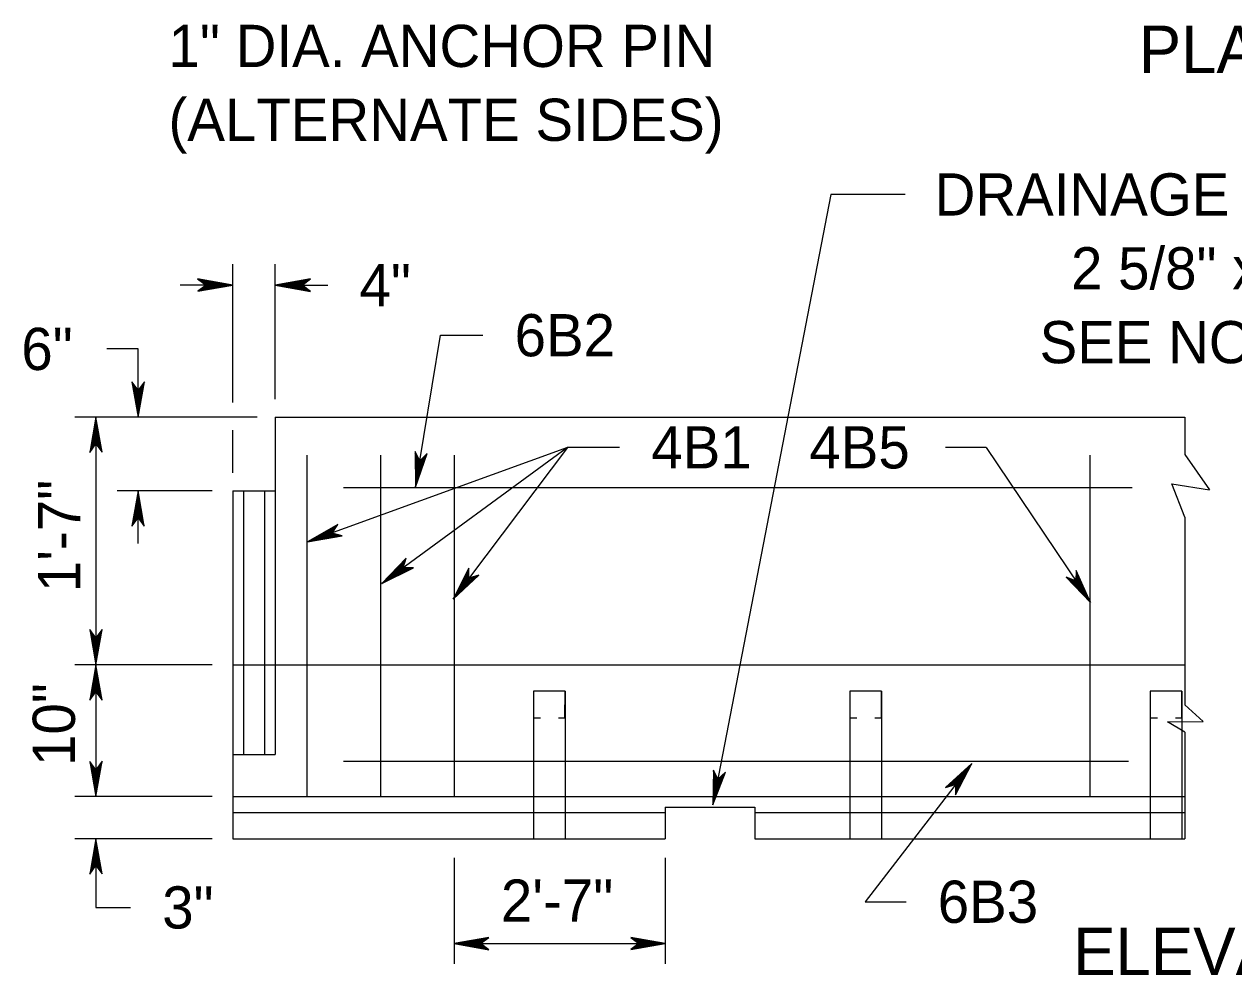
# Model space of a CAD drawing. Extents: x 499866 to 500993, y 499985 to 500645.
# Drawn here: x 500246.6 to 500361.2, y 500116.7 to 500206.9 of the extents above; entities that cross this region are included whole.
import ezdxf

# ---------------------------------------------------------------- set-up
doc = ezdxf.new("R2010")
doc.units = 0
doc.layers.add('24', color=7, linetype='Continuous')
doc.layers.add('5', color=7, linetype='Continuous')

msp = doc.modelspace()

# ---------------------------------------------------------------- linework, layer by layer
at = {"layer": '24'}
for points in [[(500266.37, 500182.17), (500263.02, 500182.77), (500263.82, 500182.17), (500263.03, 500181.59), (500266.37, 500182.17), (500266.15, 500182.17), (500263.11, 500182.72), (500263.88, 500182.17), (500263.17, 500181.64), (500266.02, 500182.16), (500265.91, 500182.17), (500263.31, 500182.64), (500263.9, 500182.17), (500263.3, 500181.71), (500265.86, 500182.18), (500265.75, 500182.16), (500263.48, 500182.57), (500263.92, 500182.18), (500263.47, 500181.77), (500265.43, 500182.16), (500265.24, 500182.16), (500263.65, 500182.48), (500263.96, 500182.18), (500263.62, 500181.85), (500265.2, 500182.17), (500265.03, 500182.19), (500263.83, 500182.39), (500264.06, 500182.16), (500263.81, 500181.93), (500264.86, 500182.17), (500264.69, 500182.19), (500263.97, 500182.33), (500264.09, 500182.17), (500263.9, 500181.99), (500264.61, 500182.18), (500264.14, 500182.29), (500264.2, 500182.16), (500264, 500182.03), (500264.49, 500182.16), (500264.18, 500182.23), (500264.31, 500182.13), (500264.16, 500182.07), (500264.31, 500182.17), (500264.23, 500182.18)], [(500270.36, 500182.17), (500273.71, 500181.58), (500272.91, 500182.17), (500273.7, 500182.76), (500270.36, 500182.17), (500270.59, 500182.18), (500273.62, 500181.63), (500272.85, 500182.18), (500273.56, 500182.71), (500270.71, 500182.19), (500270.82, 500182.17), (500273.42, 500181.71), (500272.83, 500182.18), (500273.43, 500182.64), (500270.87, 500182.17), (500270.98, 500182.19), (500273.25, 500181.78), (500272.81, 500182.17), (500273.26, 500182.58), (500271.3, 500182.19), (500271.49, 500182.19), (500273.08, 500181.87), (500272.77, 500182.17), (500273.11, 500182.5), (500271.53, 500182.17), (500271.71, 500182.16), (500272.9, 500181.96), (500272.67, 500182.19), (500272.92, 500182.42), (500271.87, 500182.17), (500272.04, 500182.16), (500272.76, 500182.02), (500272.64, 500182.18), (500272.83, 500182.36), (500272.13, 500182.17), (500272.59, 500182.06), (500272.53, 500182.19), (500272.73, 500182.32), (500272.24, 500182.19), (500272.55, 500182.11), (500272.42, 500182.22), (500272.57, 500182.28), (500272.42, 500182.18), (500272.5, 500182.17)], [(500283.66, 500163.04), (500286.03, 500177.43), (500290.06, 500177.43)], [(500257.37, 500169.67), (500257.97, 500173.02), (500257.37, 500172.21), (500256.79, 500173), (500257.37, 500169.67), (500257.37, 500169.89), (500257.92, 500172.92), (500257.37, 500172.15), (500256.84, 500172.86), (500257.36, 500170.01), (500257.37, 500170.12), (500257.84, 500172.72), (500257.37, 500172.13), (500256.91, 500172.73), (500257.37, 500170.17), (500257.36, 500170.28), (500257.77, 500172.55), (500257.37, 500172.11), (500256.97, 500172.56), (500257.36, 500170.6), (500257.36, 500170.79), (500257.68, 500172.38), (500257.38, 500172.08), (500257.05, 500172.41), (500257.37, 500170.83), (500257.38, 500171.01), (500257.59, 500172.2), (500257.36, 500171.97), (500257.13, 500172.22), (500257.37, 500171.17), (500257.39, 500171.34), (500257.53, 500172.06), (500257.37, 500171.94), (500257.19, 500172.14), (500257.37, 500171.43), (500257.49, 500171.9), (500257.36, 500171.83), (500257.23, 500172.03), (500257.36, 500171.54), (500257.43, 500171.85), (500257.33, 500171.72), (500257.27, 500171.87), (500257.37, 500171.72), (500257.38, 500171.8)], [(500253.38, 500169.67), (500252.79, 500166.31), (500253.38, 500167.12), (500253.96, 500166.33), (500253.38, 500169.67), (500253.38, 500169.44), (500252.83, 500166.41), (500253.38, 500167.18), (500253.91, 500166.47), (500253.39, 500169.32), (500253.38, 500169.21), (500252.92, 500166.61), (500253.38, 500167.2), (500253.84, 500166.6), (500253.38, 500169.16), (500253.39, 500169.05), (500252.98, 500166.78), (500253.38, 500167.22), (500253.79, 500166.77), (500253.39, 500168.73), (500253.39, 500168.54), (500253.07, 500166.95), (500253.37, 500167.25), (500253.7, 500166.92), (500253.38, 500168.5), (500253.37, 500168.32), (500253.16, 500167.13), (500253.39, 500167.36), (500253.62, 500167.11), (500253.38, 500168.16), (500253.36, 500167.99), (500253.22, 500167.27), (500253.38, 500167.39), (500253.56, 500167.19), (500253.38, 500167.9), (500253.27, 500167.43), (500253.39, 500167.5), (500253.52, 500167.3), (500253.39, 500167.79), (500253.32, 500167.48), (500253.42, 500167.61), (500253.48, 500167.46), (500253.38, 500167.61), (500253.37, 500167.53)], [(500283.66, 500163.04), (500284.78, 500166.22), (500284.07, 500165.53), (500283.63, 500166.39), (500283.66, 500163.04), (500283.69, 500163.26), (500284.72, 500166.14), (500284.06, 500165.47), (500283.65, 500166.25), (500283.7, 500163.38), (500283.74, 500163.48), (500284.61, 500165.95), (500284.05, 500165.46), (500283.71, 500166.12), (500283.75, 500163.53), (500283.75, 500163.64), (500284.51, 500165.8), (500284.06, 500165.43), (500283.73, 500165.94), (500283.8, 500163.96), (500283.83, 500164.15), (500284.4, 500165.65), (500284.06, 500165.4), (500283.79, 500165.78), (500283.85, 500164.18), (500283.89, 500164.35), (500284.28, 500165.49), (500284.02, 500165.3), (500283.83, 500165.58), (500283.91, 500164.51), (500283.95, 500164.67), (500284.2, 500165.36), (500284.02, 500165.27), (500283.88, 500165.49), (500283.95, 500164.76), (500284.13, 500165.2), (500284, 500165.16), (500283.9, 500165.38), (500283.95, 500164.88), (500284.07, 500165.17), (500283.95, 500165.06), (500283.92, 500165.21), (500283.99, 500165.05), (500284.02, 500165.13)], [(500257.37, 500162.67), (500256.78, 500159.32), (500257.37, 500160.12), (500257.96, 500159.34), (500257.37, 500162.67), (500257.38, 500162.45), (500256.83, 500159.41), (500257.38, 500160.18), (500257.91, 500159.47), (500257.39, 500162.33), (500257.37, 500162.22), (500256.91, 500159.62), (500257.38, 500160.2), (500257.84, 500159.6), (500257.37, 500162.17), (500257.39, 500162.05), (500256.98, 500159.78), (500257.37, 500160.22), (500257.78, 500159.77), (500257.39, 500161.73), (500257.39, 500161.54), (500257.06, 500159.95), (500257.36, 500160.26), (500257.7, 500159.93), (500257.37, 500161.51), (500257.36, 500161.33), (500257.16, 500160.13), (500257.39, 500160.36), (500257.62, 500160.11), (500257.37, 500161.16), (500257.36, 500161), (500257.22, 500160.28), (500257.38, 500160.4), (500257.56, 500160.2), (500257.37, 500160.91), (500257.26, 500160.44), (500257.39, 500160.51), (500257.52, 500160.3), (500257.39, 500160.79), (500257.31, 500160.48), (500257.42, 500160.61), (500257.48, 500160.46), (500257.38, 500160.61), (500257.36, 500160.53)], [(500273.44, 500157.83), (500276.72, 500158.41), (500275.78, 500158.68), (500276.31, 500159.48), (500273.44, 500157.83), (500273.64, 500157.91), (500276.62, 500158.42), (500275.72, 500158.67), (500276.2, 500159.39), (500273.75, 500157.96), (500273.86, 500157.98), (500276.4, 500158.43), (500275.71, 500158.66), (500276.11, 500159.28), (500273.91, 500158), (500274, 500158.05), (500276.23, 500158.44), (500275.69, 500158.65), (500275.97, 500159.17), (500274.3, 500158.16), (500274.47, 500158.22), (500276.04, 500158.46), (500275.66, 500158.63), (500275.85, 500159.05), (500274.51, 500158.22), (500274.68, 500158.27), (500275.84, 500158.48), (500275.56, 500158.62), (500275.71, 500158.91), (500274.82, 500158.33), (500274.99, 500158.38), (500275.69, 500158.49), (500275.53, 500158.6), (500275.65, 500158.83), (500275.06, 500158.42), (500275.53, 500158.47), (500275.42, 500158.57), (500275.57, 500158.76), (500275.16, 500158.48), (500275.47, 500158.51), (500275.32, 500158.56), (500275.43, 500158.66), (500275.33, 500158.53), (500275.41, 500158.54)], [(500273.44, 500157.83), (500276.72, 500158.41), (500275.78, 500158.68), (500276.31, 500159.48), (500273.44, 500157.83), (500273.64, 500157.91), (500276.62, 500158.42), (500275.72, 500158.67), (500276.2, 500159.39), (500273.75, 500157.96), (500273.86, 500157.98), (500276.4, 500158.43), (500275.71, 500158.66), (500276.11, 500159.28), (500273.91, 500158), (500274, 500158.05), (500276.23, 500158.44), (500275.69, 500158.65), (500275.97, 500159.17), (500274.3, 500158.16), (500274.47, 500158.22), (500276.04, 500158.46), (500275.66, 500158.63), (500275.85, 500159.05), (500274.51, 500158.22), (500274.68, 500158.27), (500275.84, 500158.48), (500275.56, 500158.62), (500275.71, 500158.91), (500274.82, 500158.33), (500274.99, 500158.38), (500275.69, 500158.49), (500275.53, 500158.6), (500275.65, 500158.83), (500275.06, 500158.42), (500275.53, 500158.47), (500275.42, 500158.57), (500275.57, 500158.76), (500275.16, 500158.48), (500275.47, 500158.51), (500275.32, 500158.56), (500275.43, 500158.66), (500275.33, 500158.53), (500275.41, 500158.54)], [(500280.49, 500153.9), (500283.48, 500155.37), (500282.5, 500155.37), (500282.78, 500156.28), (500280.49, 500153.9), (500280.67, 500154.03), (500283.38, 500155.35), (500282.45, 500155.34), (500282.7, 500156.17), (500280.75, 500154.11), (500280.85, 500154.16), (500283.17, 500155.3), (500282.44, 500155.33), (500282.64, 500156.04), (500280.89, 500154.19), (500280.97, 500154.27), (500283, 500155.26), (500282.42, 500155.31), (500282.54, 500155.89), (500281.22, 500154.45), (500281.37, 500154.56), (500282.81, 500155.23), (500282.4, 500155.28), (500282.47, 500155.74), (500281.41, 500154.57), (500281.56, 500154.66), (500282.62, 500155.19), (500282.3, 500155.24), (500282.37, 500155.57), (500281.68, 500154.77), (500281.82, 500154.85), (500282.47, 500155.16), (500282.28, 500155.22), (500282.33, 500155.47), (500281.88, 500154.91), (500282.32, 500155.1), (500282.19, 500155.16), (500282.28, 500155.38), (500281.97, 500155), (500282.25, 500155.11), (500282.09, 500155.12), (500282.17, 500155.25), (500282.11, 500155.09), (500282.18, 500155.12)], [(500280.49, 500153.9), (500283.48, 500155.37), (500282.5, 500155.37), (500282.78, 500156.28), (500280.49, 500153.9), (500280.67, 500154.03), (500283.38, 500155.35), (500282.45, 500155.34), (500282.7, 500156.17), (500280.75, 500154.11), (500280.85, 500154.16), (500283.17, 500155.3), (500282.44, 500155.33), (500282.64, 500156.04), (500280.89, 500154.19), (500280.97, 500154.27), (500283, 500155.26), (500282.42, 500155.31), (500282.54, 500155.89), (500281.22, 500154.45), (500281.37, 500154.56), (500282.81, 500155.23), (500282.4, 500155.28), (500282.47, 500155.74), (500281.41, 500154.57), (500281.56, 500154.66), (500282.62, 500155.19), (500282.3, 500155.24), (500282.37, 500155.57), (500281.68, 500154.77), (500281.82, 500154.85), (500282.47, 500155.16), (500282.28, 500155.22), (500282.33, 500155.47), (500281.88, 500154.91), (500282.32, 500155.1), (500282.19, 500155.16), (500282.28, 500155.38), (500281.97, 500155), (500282.25, 500155.11), (500282.09, 500155.12), (500282.17, 500155.25), (500282.11, 500155.09), (500282.18, 500155.12)], [(500287.23, 500152.42), (500289.66, 500154.69), (500288.73, 500154.41), (500288.73, 500155.36), (500287.23, 500152.42), (500287.35, 500152.6), (500289.57, 500154.64), (500288.68, 500154.37), (500288.69, 500155.23), (500287.41, 500152.7), (500287.49, 500152.77), (500289.38, 500154.53), (500288.67, 500154.35), (500288.67, 500155.09), (500287.52, 500152.81), (500287.57, 500152.91), (500289.23, 500154.44), (500288.66, 500154.33), (500288.61, 500154.92), (500287.77, 500153.16), (500287.88, 500153.31), (500289.07, 500154.36), (500288.65, 500154.3), (500288.59, 500154.75), (500287.91, 500153.33), (500288.02, 500153.46), (500288.89, 500154.27), (500288.57, 500154.23), (500288.54, 500154.56), (500288.11, 500153.6), (500288.22, 500153.72), (500288.75, 500154.2), (500288.56, 500154.2), (500288.53, 500154.46), (500288.26, 500153.79), (500288.62, 500154.1), (500288.48, 500154.12), (500288.51, 500154.35), (500288.32, 500153.9), (500288.56, 500154.09), (500288.4, 500154.05), (500288.44, 500154.2), (500288.43, 500154.03), (500288.49, 500154.08)], [(500347.63, 500152.09), (500346.28, 500155.14), (500346.24, 500154.16), (500345.34, 500154.48), (500347.63, 500152.09), (500347.5, 500152.27), (500346.3, 500155.04), (500346.27, 500154.11), (500345.45, 500154.4), (500347.43, 500152.36), (500347.38, 500152.46), (500346.34, 500154.82), (500346.28, 500154.09), (500345.58, 500154.33), (500347.35, 500152.5), (500347.28, 500152.59), (500346.37, 500154.65), (500346.3, 500154.08), (500345.72, 500154.22), (500347.1, 500152.85), (500347, 500153), (500346.4, 500154.47), (500346.32, 500154.06), (500345.87, 500154.14), (500346.99, 500153.04), (500346.91, 500153.19), (500346.42, 500154.27), (500346.36, 500153.96), (500346.04, 500154.03), (500346.81, 500153.32), (500346.73, 500153.46), (500346.45, 500154.12), (500346.38, 500153.94), (500346.13, 500154), (500346.67, 500153.52), (500346.5, 500153.96), (500346.44, 500153.84), (500346.22, 500153.94), (500346.59, 500153.61), (500346.49, 500153.9), (500346.47, 500153.74), (500346.34, 500153.83), (500346.5, 500153.76), (500346.47, 500153.83)], [(500253.38, 500146.18), (500253.97, 500149.53), (500253.38, 500148.73), (500252.79, 500149.52), (500253.38, 500146.18), (500253.37, 500146.41), (500253.93, 500149.44), (500253.37, 500148.67), (500252.84, 500149.38), (500253.36, 500146.53), (500253.38, 500146.64), (500253.84, 500149.24), (500253.37, 500148.65), (500252.92, 500149.25), (500253.38, 500146.69), (500253.36, 500146.8), (500253.77, 500149.07), (500253.38, 500148.63), (500252.97, 500149.08), (500253.36, 500147.12), (500253.36, 500147.31), (500253.69, 500148.9), (500253.39, 500148.59), (500253.05, 500148.93), (500253.38, 500147.35), (500253.39, 500147.52), (500253.59, 500148.72), (500253.36, 500148.49), (500253.13, 500148.74), (500253.38, 500147.69), (500253.39, 500147.86), (500253.53, 500148.58), (500253.37, 500148.46), (500253.19, 500148.65), (500253.38, 500147.94), (500253.49, 500148.41), (500253.36, 500148.35), (500253.23, 500148.55), (500253.36, 500148.06), (500253.44, 500148.37), (500253.34, 500148.24), (500253.28, 500148.39), (500253.37, 500148.24), (500253.39, 500148.32)], [(500253.38, 500146.18), (500252.79, 500142.83), (500253.38, 500143.63), (500253.96, 500142.85), (500253.38, 500146.18), (500253.38, 500145.96), (500252.83, 500142.93), (500253.38, 500143.7), (500253.91, 500142.99), (500253.39, 500145.84), (500253.38, 500145.73), (500252.92, 500143.13), (500253.38, 500143.71), (500253.84, 500143.11), (500253.38, 500145.68), (500253.39, 500145.57), (500252.98, 500143.29), (500253.38, 500143.74), (500253.79, 500143.29), (500253.39, 500145.24), (500253.39, 500145.05), (500253.07, 500143.46), (500253.37, 500143.77), (500253.7, 500143.44), (500253.38, 500145.02), (500253.37, 500144.84), (500253.16, 500143.65), (500253.39, 500143.88), (500253.62, 500143.63), (500253.38, 500144.68), (500253.36, 500144.51), (500253.22, 500143.79), (500253.38, 500143.91), (500253.56, 500143.71), (500253.38, 500144.42), (500253.27, 500143.95), (500253.39, 500144.02), (500253.52, 500143.81), (500253.39, 500144.3), (500253.32, 500144), (500253.42, 500144.12), (500253.48, 500143.98), (500253.38, 500144.12), (500253.37, 500144.05)], [(500253.38, 500133.69), (500253.97, 500137.04), (500253.38, 500136.24), (500252.79, 500137.02), (500253.38, 500133.69), (500253.37, 500133.91), (500253.93, 500136.95), (500253.37, 500136.18), (500252.84, 500136.89), (500253.36, 500134.03), (500253.38, 500134.15), (500253.84, 500136.75), (500253.37, 500136.16), (500252.92, 500136.76), (500253.38, 500134.2), (500253.36, 500134.31), (500253.77, 500136.58), (500253.38, 500136.14), (500252.97, 500136.59), (500253.36, 500134.63), (500253.36, 500134.82), (500253.69, 500136.41), (500253.39, 500136.1), (500253.05, 500136.44), (500253.38, 500134.85), (500253.39, 500135.03), (500253.59, 500136.23), (500253.36, 500136), (500253.13, 500136.25), (500253.38, 500135.2), (500253.39, 500135.37), (500253.53, 500136.09), (500253.37, 500135.97), (500253.19, 500136.16), (500253.38, 500135.45), (500253.49, 500135.92), (500253.36, 500135.85), (500253.23, 500136.06), (500253.36, 500135.57), (500253.44, 500135.88), (500253.34, 500135.75), (500253.28, 500135.9), (500253.37, 500135.75), (500253.39, 500135.83)], [(500311.85, 500132.9), (500313.04, 500136.01), (500312.32, 500135.35), (500311.91, 500136.21), (500311.85, 500132.9), (500311.88, 500133.12), (500312.98, 500135.92), (500312.3, 500135.29), (500311.92, 500136.07), (500311.89, 500133.23), (500311.93, 500133.34), (500312.86, 500135.75), (500312.3, 500135.27), (500311.97, 500135.93), (500311.94, 500133.39), (500311.95, 500133.5), (500312.76, 500135.6), (500312.3, 500135.25), (500311.99, 500135.76), (500312, 500133.81), (500312.04, 500133.99), (500312.65, 500135.45), (500312.3, 500135.21), (500312.04, 500135.59), (500312.06, 500134.02), (500312.11, 500134.19), (500312.52, 500135.3), (500312.26, 500135.12), (500312.08, 500135.4), (500312.13, 500134.35), (500312.17, 500134.51), (500312.44, 500135.17), (500312.26, 500135.09), (500312.13, 500135.31), (500312.17, 500134.59), (500312.37, 500135.02), (500312.23, 500134.98), (500312.15, 500135.2), (500312.18, 500134.71), (500312.31, 500134.99), (500312.19, 500134.89), (500312.16, 500135.04), (500312.22, 500134.88), (500312.25, 500134.95)], [(500336.39, 500136.84), (500326.29, 500123.73), (500330.16, 500123.73)], [(500336.39, 500136.84), (500333.9, 500134.56), (500334.84, 500134.83), (500334.83, 500133.86), (500336.39, 500136.84), (500336.26, 500136.66), (500333.99, 500134.61), (500334.89, 500134.88), (500334.88, 500134), (500336.19, 500136.56), (500336.11, 500136.48), (500334.18, 500134.72), (500334.9, 500134.89), (500334.89, 500134.14), (500336.08, 500136.44), (500336.03, 500136.34), (500334.33, 500134.8), (500334.91, 500134.91), (500334.96, 500134.31), (500335.83, 500136.09), (500335.72, 500135.94), (500334.5, 500134.89), (500334.92, 500134.95), (500334.98, 500134.48), (500335.69, 500135.92), (500335.57, 500135.79), (500334.68, 500134.97), (500335.01, 500135.01), (500335.03, 500134.68), (500335.48, 500135.65), (500335.36, 500135.53), (500334.82, 500135.05), (500335.02, 500135.04), (500335.04, 500134.78), (500335.32, 500135.45), (500334.95, 500135.15), (500335.09, 500135.13), (500335.07, 500134.89), (500335.26, 500135.35), (500335.02, 500135.15), (500335.17, 500135.19), (500335.13, 500135.04), (500335.15, 500135.21), (500335.09, 500135.16)], [(500253.38, 500129.7), (500252.79, 500126.35), (500253.38, 500127.15), (500253.96, 500126.36), (500253.38, 500129.7), (500253.38, 500129.47), (500252.83, 500126.44), (500253.38, 500127.21), (500253.91, 500126.5), (500253.39, 500129.35), (500253.38, 500129.24), (500252.92, 500126.64), (500253.38, 500127.23), (500253.84, 500126.63), (500253.38, 500129.19), (500253.39, 500129.08), (500252.98, 500126.81), (500253.38, 500127.25), (500253.79, 500126.8), (500253.39, 500128.76), (500253.39, 500128.57), (500253.07, 500126.98), (500253.37, 500127.29), (500253.7, 500126.95), (500253.38, 500128.53), (500253.37, 500128.35), (500253.16, 500127.16), (500253.39, 500127.39), (500253.62, 500127.14), (500253.38, 500128.19), (500253.36, 500128.02), (500253.22, 500127.3), (500253.38, 500127.42), (500253.56, 500127.23), (500253.38, 500127.93), (500253.27, 500127.46), (500253.39, 500127.53), (500253.52, 500127.33), (500253.39, 500127.82), (500253.32, 500127.51), (500253.42, 500127.64), (500253.48, 500127.49), (500253.38, 500127.64), (500253.37, 500127.56)], [(500287.34, 500119.76), (500290.62, 500119.18), (500289.84, 500119.76), (500290.6, 500120.33), (500287.34, 500119.76), (500287.56, 500119.77), (500290.53, 500119.23), (500289.78, 500119.77), (500290.47, 500120.29), (500287.68, 500119.78), (500287.79, 500119.76), (500290.33, 500119.31), (500289.76, 500119.77), (500290.34, 500120.21), (500287.84, 500119.76), (500287.95, 500119.78), (500290.17, 500119.38), (500289.74, 500119.76), (500290.18, 500120.16), (500288.26, 500119.78), (500288.45, 500119.78), (500290, 500119.46), (500289.7, 500119.75), (500290.03, 500120.08), (500288.48, 500119.76), (500288.66, 500119.75), (500289.82, 500119.55), (500289.6, 500119.78), (500289.84, 500120), (500288.82, 500119.76), (500288.98, 500119.75), (500289.68, 500119.61), (500289.57, 500119.77), (500289.76, 500119.94), (500289.07, 500119.76), (500289.52, 500119.65), (500289.46, 500119.78), (500289.66, 500119.9), (500289.18, 500119.78), (500289.48, 500119.7), (500289.36, 500119.8), (500289.5, 500119.86), (500289.36, 500119.77), (500289.43, 500119.75)], [(500307.34, 500119.76), (500304.06, 500120.34), (500304.84, 500119.76), (500304.08, 500119.19), (500307.34, 500119.76), (500307.12, 500119.76), (500304.15, 500120.3), (500304.91, 500119.76), (500304.21, 500119.24), (500307, 500119.75), (500306.89, 500119.76), (500304.35, 500120.21), (500304.92, 500119.76), (500304.34, 500119.31), (500306.84, 500119.76), (500306.73, 500119.75), (500304.51, 500120.15), (500304.95, 500119.76), (500304.5, 500119.36), (500306.42, 500119.75), (500306.23, 500119.75), (500304.68, 500120.06), (500304.98, 500119.77), (500304.66, 500119.45), (500306.2, 500119.76), (500306.03, 500119.77), (500304.86, 500119.97), (500305.08, 500119.75), (500304.84, 500119.52), (500305.86, 500119.76), (500305.7, 500119.78), (500305, 500119.91), (500305.11, 500119.76), (500304.92, 500119.58), (500305.61, 500119.76), (500305.16, 500119.87), (500305.22, 500119.75), (500305.02, 500119.62), (500305.5, 500119.75), (500305.2, 500119.82), (500305.32, 500119.72), (500305.18, 500119.66), (500305.32, 500119.76), (500305.25, 500119.77)]]:
    msp.add_lwpolyline(points, dxfattribs=at)
at = {"layer": '5'}
for p, q in [((500266.37, 500171.04), (500266.37, 500184.17)), ((500270.36, 500171.38), (500270.36, 500184.17)), ((500266.37, 500182.17), (500261.37, 500182.17)), ((500270.36, 500182.17), (500275.36, 500182.17)), ((500268.67, 500169.67), (500251.38, 500169.67)), ((500253.38, 500169.67), (500253.38, 500146.18)), ((500270.36, 500169.67), (500356.58, 500169.67)), ((500270.36, 500169.67), (500270.36, 500162.67)), ((500356.58, 500169.67), (500356.58, 500166.12)), ((500266.37, 500164.37), (500266.37, 500168.43)), ((500273.36, 500166.05), (500273.36, 500133.69)), ((500280.35, 500166.05), (500280.35, 500133.69)), ((500298.07, 500166.8), (500280.49, 500153.9)), ((500298.07, 500166.8), (500287.23, 500152.42)), ((500287.34, 500166.05), (500287.34, 500133.69)), ((500347.58, 500166.05), (500347.58, 500133.69)), ((500356.58, 500166.12), (500358.9, 500162.76)), ((500264.39, 500162.67), (500255.38, 500162.67)), ((500257.37, 500157.67), (500257.37, 500162.67)), ((500266.37, 500162.67), (500266.37, 500129.7)), ((500266.37, 500162.67), (500270.36, 500162.67)), ((500267.37, 500162.67), (500267.37, 500137.69)), ((500269.37, 500162.67), (500269.37, 500137.69)), ((500270.36, 500162.67), (500270.36, 500137.69)), ((500276.84, 500162.98), (500351.58, 500162.98)), ((500356.58, 500160.19), (500355.33, 500163.35)), ((500355.33, 500163.35), (500358.9, 500162.76)), ((500356.58, 500160.19), (500356.58, 500142.38)), ((500264.39, 500146.18), (500251.38, 500146.18)), ((500253.38, 500146.18), (500253.38, 500133.69)), ((500266.37, 500146.18), (500356.58, 500146.18)), ((500294.84, 500143.68), (500294.84, 500129.7)), ((500297.84, 500143.68), (500297.84, 500129.7)), ((500324.82, 500143.68), (500324.82, 500129.7)), ((500327.82, 500143.68), (500327.82, 500129.7)), ((500353.3, 500143.68), (500353.3, 500129.7)), ((500356.3, 500143.68), (500356.3, 500129.7)), ((500356.58, 500142.38), (500358.3, 500140.8)), ((500354.92, 500140.78), (500358.3, 500140.8)), ((500356.58, 500139.81), (500354.92, 500140.78)), ((500356.58, 500139.81), (500356.58, 500129.7)), ((500266.37, 500137.69), (500270.36, 500137.69)), ((500276.84, 500137.05), (500351.25, 500137.05)), ((500264.39, 500133.69), (500251.38, 500133.69)), ((500266.37, 500133.69), (500356.58, 500133.69)), ((500307.34, 500132.69), (500315.83, 500132.69)), ((500307.34, 500132.69), (500307.34, 500129.7)), ((500315.83, 500132.69), (500315.83, 500129.7)), ((500266.37, 500132.19), (500307.34, 500132.19)), ((500315.83, 500132.19), (500356.58, 500132.19)), ((500264.39, 500129.7), (500251.38, 500129.7)), ((500266.37, 500129.7), (500307.34, 500129.7)), ((500315.83, 500129.7), (500356.58, 500129.7)), ((500287.34, 500127.89), (500287.34, 500117.85)), ((500307.34, 500127.89), (500307.34, 500117.85)), ((500287.34, 500119.76), (500307.34, 500119.76))]:
    msp.add_line(p, q, dxfattribs=at)
for points in [[(500330.06, 500190.77), (500323.02, 500190.77), (500311.85, 500132.9)], [(500257.37, 500169.67), (500257.37, 500176.13), (500254.42, 500176.13)], [(500303.01, 500166.8), (500298.07, 500166.8), (500273.44, 500157.83)], [(500337.76, 500166.8), (500333.9, 500166.8)], [(500337.76, 500166.8), (500347.63, 500152.09)], [(500297.22, 500141.17), (500297.83, 500141.17), (500297.84, 500143.68), (500294.84, 500143.68)], [(500294.84, 500143.68), (500294.84, 500141.17), (500295.52, 500141.17)], [(500327.21, 500141.17), (500327.82, 500141.17), (500327.82, 500143.68), (500324.82, 500143.68)], [(500324.82, 500143.68), (500324.82, 500141.17), (500325.5, 500141.17)], [(500355.68, 500141.17), (500356.29, 500141.17), (500356.3, 500143.68), (500353.3, 500143.68)], [(500353.3, 500143.68), (500353.3, 500141.17), (500353.98, 500141.17)], [(500253.38, 500129.7), (500253.38, 500123.19), (500256.66, 500123.19)]]:
    msp.add_lwpolyline(points, dxfattribs=at)

# ---------------------------------------------------------------- texts
for s, height, p in [('1" DIA. ANCHOR PIN', 4, (500260.26, 500202.85)), ('PLAN', 4.5, (500352.21, 500202.27)), ('(ALTERNATE SIDES)', 4, (500260.26, 500195.85)), ('DRAINAGE POCKET', 4, (500332.86, 500188.77)), ('2 5/8" x 5 1/2"', 4, (500345.79, 500181.77)), ('4"', 4, (500278.36, 500180.17)), ('6B2', 4, (500293.06, 500175.43)), ('SEE NOTE 9', 4, (500342.81, 500174.77)), ('6"', 4, (500246.31, 500174.13)), ('4B1', 4, (500306.01, 500164.8)), ('4B5', 4, (500320.99, 500164.8)), ('2\'-7"', 4, (500291.76, 500121.84)), ('6B3', 4, (500333.16, 500121.73)), ('3"', 4, (500259.66, 500121.19)), ('ELEVATION', 4.5, (500346, 500116.77))]:
    msp.add_text(s, height=height, dxfattribs=at).set_placement(p)
for s, p in [('1\'-7"', (500251.89, 500153.07)), ('10"', (500251.39, 500136.6))]:
    msp.add_text(s, height=4, rotation=90, dxfattribs=at).set_placement(p)

doc.saveas('drawing.dxf')
